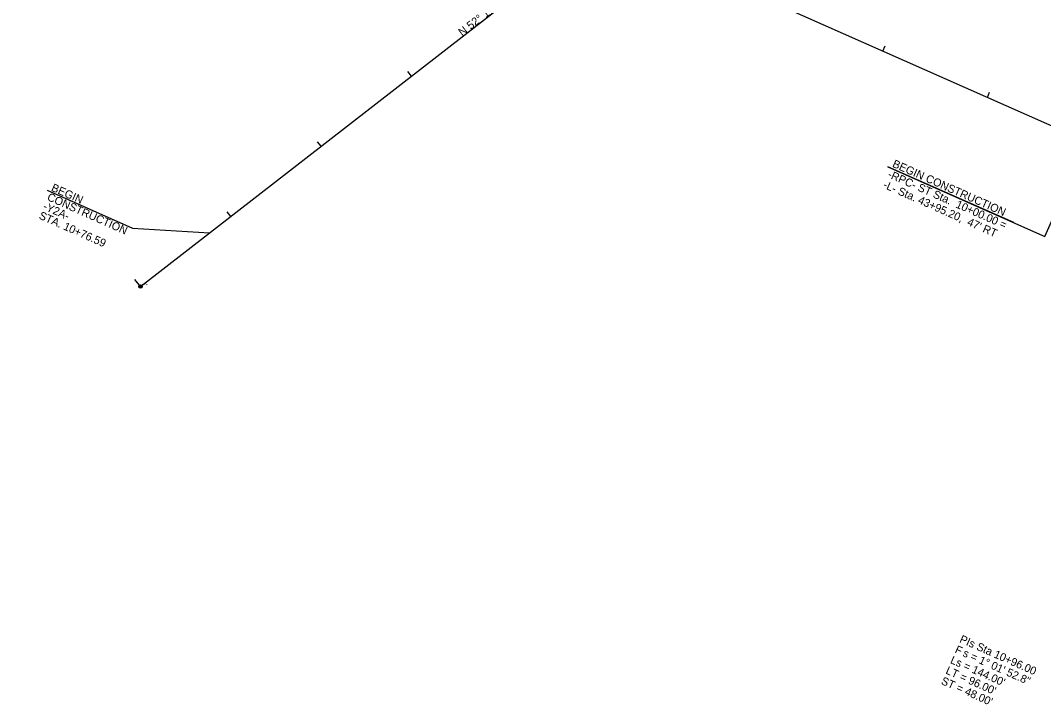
# Model space of a CAD drawing. Extents: x 1636713 to 1642783, y 841520 to 844371.
# Drawn here: x 1639007 to 1639901, y 842320 to 842918 of the extents above; entities that cross this region are included whole.
import ezdxf

# ---------------------------------------------------------------- set-up
doc = ezdxf.new("R2010")
doc.units = 0
for name, color, linetype in [('COGO Default Chain', 7, 'Continuous'), ('Cogo Default Point CELL', 7, 'Continuous'), ('COGO Default Point Number', 7, 'Continuous'), ('Prop Horizontal Alignment', 7, 'Continuous'), ('Prop Horizontal Alignment Curve and Spiral Data', 7, 'Continuous'), ('Prop Horizontal Alignment Direction Label', 7, 'Continuous'), ('Prop Horizontal Alignment Station Label', 7, 'Continuous'), ('Prop Horizontal Alignment Tick Large', 7, 'Continuous'), ('Prop Horizontal Alignment Tick Small', 7, 'Continuous')]:
    doc.layers.add(name, color=color, linetype=linetype)

msp = doc.modelspace()

# ---------------------------------------------------------------- linework, layer by layer
at = {"layer": 'COGO Default Chain'}
msp.add_line((1639111.65, 842685.24), (1639731.27, 843166.33), dxfattribs=at)
at = {"layer": 'Cogo Default Point CELL'}
for points in [[(1639110.15, 842685.24), (1639111.65, 842685.24)], [(1639111.65, 842686.74), (1639111.65, 842685.24)], [(1639111.65, 842685.24), (1639113.15, 842685.24)], [(1639111.65, 842685.24), (1639111.65, 842683.74)]]:
    msp.add_lwpolyline(points, dxfattribs=at)
msp.add_circle((1639111.65, 842685.24), 1.17, dxfattribs=at)
at = {"layer": 'Prop Horizontal Alignment'}
for p, q in [((1638900.9, 843272.49), (1640357.88, 842626.45)), ((1639111.65, 842685.24), (1639731.27, 843166.33))]:
    msp.add_line(p, q, dxfattribs=at)
at = {"layer": 'Prop Horizontal Alignment Station Label'}
msp.add_line((1639875.36, 842741.14), (1639765.22, 842789.98), dxfattribs=at)
for points in [[(1639765.22, 842789.98), (1639902.6, 842729.07), (1639918.97, 842766.37)], [(1639030.04, 842769.45), (1639104.57, 842736.36), (1639172.14, 842732.21)]]:
    msp.add_lwpolyline(points, dxfattribs=at)
msp.add_circle((1639111.65, 842685.24), 1.5, dxfattribs=at)
at = {"layer": 'Prop Horizontal Alignment Tick Large'}
msp.add_line((1639111.65, 842685.24), (1639106.74, 842691.56), dxfattribs=at)
at = {"layer": 'Prop Horizontal Alignment Tick Small'}
for p, q in [((1639760.79, 842891.21), (1639762.82, 842895.78)), ((1639348.61, 842869.22), (1639345.54, 842873.17)), ((1639852.21, 842850.67), (1639854.23, 842855.24)), ((1639269.62, 842807.89), (1639266.55, 842811.84)), ((1639190.63, 842746.56), (1639187.57, 842750.51))]:
    msp.add_line(p, q, dxfattribs=at)

# ---------------------------------------------------------------- texts
at = {"layer": 'COGO Default Point Number'}
msp.add_text('15200', height=1.25, dxfattribs=at).set_placement((1639112.9, 842686.49))
at = {"layer": 'Prop Horizontal Alignment Curve and Spiral Data'}
for s, p in [('PIs Sta 10+96.00', (1639827.32, 842374.5)), ('F', (1639823.26, 842365.36)), ("Ls = 144.00'", (1639819.21, 842356.22)), ('s = 1%%d 01\' 52.8"', (1639830.13, 842362.31)), ("LT = 96.00'", (1639815.16, 842347.07)), ("ST = 48.00'", (1639811.1, 842337.93))]:
    msp.add_text(s, height=7, rotation=336.08714, dxfattribs=at).set_placement(p)
at = {"layer": 'Prop Horizontal Alignment Direction Label'}
msp.add_text('N 52%%d 10\' 23.1" E', height=7, rotation=37.82692, dxfattribs=at).set_placement((1639392.95, 842903.91))
at = {"layer": 'Prop Horizontal Alignment Station Label'}
for s, p in [('BEGIN CONSTRUCTION', (1639768.57, 842790.14)), ('-RPC- ST Sta.  10+00.00 =', (1639764.52, 842780.99)), ('BEGIN ', (1639032.99, 842769.21)), ("-L- Sta. 43+95.20,  47' RT", (1639760.46, 842771.85)), ('CONSTRUCTION ', (1639029.4, 842761.1)), ('-Y2A- ', (1639025.8, 842752.99)), ('STA. 10+76.59', (1639022.2, 842744.88))]:
    msp.add_text(s, height=7, rotation=336.08714, dxfattribs=at).set_placement(p)

doc.saveas('drawing.dxf')
